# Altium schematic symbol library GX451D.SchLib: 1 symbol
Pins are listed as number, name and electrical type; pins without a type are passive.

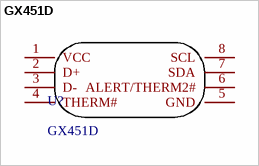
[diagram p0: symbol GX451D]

## GX451D
designator U?
footprint DFN-8_L2.0-W2.0-P0.50-BL
pins: 1 VCC, 2 D+, 3 D-, 4 THERM#, 5 GND, 6 ALERT/THERM2#, 7 SDA, 8 SCL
